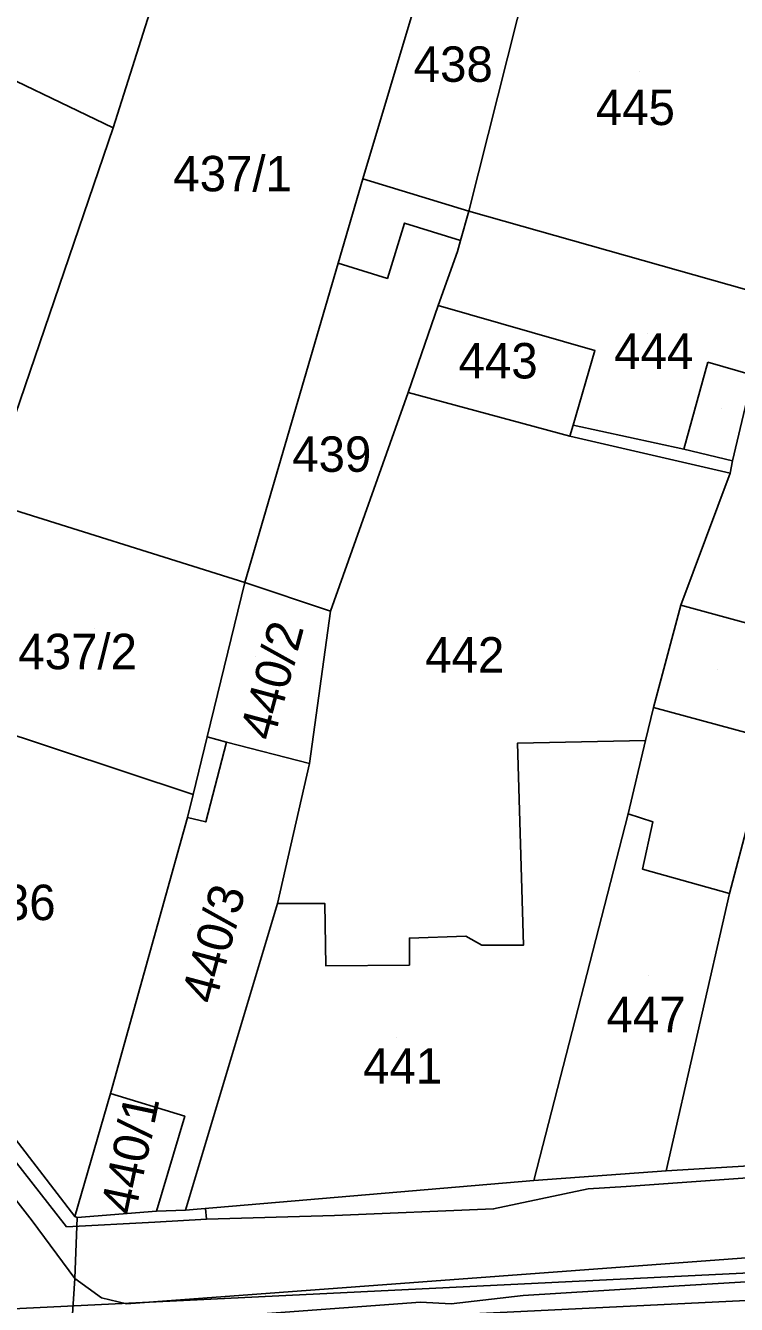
# Model space of a CAD drawing. Extents: x -263423 to -261326, y -1240067 to -1237864.
# Drawn here: x -263033.7 to -262993.6, y -1239820.5 to -1239748.3 of the extents above; entities that cross this region are included whole.
import ezdxf

# ---------------------------------------------------------------- set-up
doc = ezdxf.new("R2010")
doc.units = 0
for name, color, linetype in [('body_kn', 7, 'Continuous'), ('kladpar_druhypozemkov', 7, 'Continuous'), ('kladpar_hranice', 7, 'Continuous'), ('kladpar_parcelnecisla', 7, 'Continuous'), ('kladpar_plochy', 7, 'Continuous'), ('tarchy_linie', 7, 'Continuous'), ('zappar_hrandruhpozemk', 7, 'Continuous')]:
    doc.layers.add(name, color=color, linetype=linetype)

msp = doc.modelspace()

# ---------------------------------------------------------------- linework, layer by layer
at = {"layer": 'body_kn'}
for p, q in [((-263028.75, -1239754.07), (-263028.75, -1239754.07)), ((-263014.66, -1239756.94), (-263014.66, -1239756.94)), ((-263014.66, -1239756.94), (-263014.66, -1239756.94)), ((-263008.67, -1239758.76), (-263008.67, -1239758.76)), ((-263012.3, -1239759.44), (-263012.3, -1239759.44)), ((-263009.14, -1239760.42), (-263009.14, -1239760.42)), ((-263009.14, -1239760.42), (-263009.14, -1239760.42)), ((-263009.32, -1239761.05), (-263009.32, -1239761.05)), ((-263016.05, -1239761.7), (-263016.05, -1239761.7)), ((-263016.05, -1239761.7), (-263016.05, -1239761.7)), ((-263013.27, -1239762.56), (-263013.27, -1239762.56)), ((-263010.41, -1239764.1), (-263010.41, -1239764.1)), ((-263001.56, -1239766.63), (-263001.56, -1239766.63)), ((-263001.56, -1239766.63), (-263001.56, -1239766.63)), ((-262995.18, -1239767.3), (-262995.18, -1239767.3)), ((-263012.09, -1239769), (-263012.09, -1239769)), ((-263012.09, -1239769), (-263012.09, -1239769)), ((-263002.79, -1239770.84), (-263002.79, -1239770.84)), ((-263002.79, -1239770.84), (-263002.79, -1239770.84)), ((-263002.98, -1239771.47), (-263002.98, -1239771.47)), ((-262996.54, -1239772.2), (-262996.54, -1239772.2)), ((-262993.8, -1239772.86), (-262993.8, -1239772.86)), ((-262993.93, -1239773.56), (-262993.93, -1239773.56)), ((-263021.32, -1239779.73), (-263021.32, -1239779.73)), ((-262996.71, -1239781), (-262996.71, -1239781)), ((-263016.48, -1239781.35), (-263016.48, -1239781.35)), ((-263016.48, -1239781.35), (-263016.48, -1239781.35)), ((-262998.26, -1239786.79), (-262998.26, -1239786.79)), ((-263023.44, -1239788.44), (-263023.44, -1239788.44)), ((-263022.35, -1239788.73), (-263022.35, -1239788.73)), ((-263022.35, -1239788.73), (-263022.35, -1239788.73)), ((-263005.92, -1239788.79), (-263005.92, -1239788.79)), ((-262998.71, -1239788.64), (-262998.71, -1239788.64)), ((-263017.66, -1239789.95), (-263017.66, -1239789.95)), ((-263024.24, -1239791.7), (-263024.24, -1239791.7)), ((-263024.55, -1239792.98), (-263024.55, -1239792.98)), ((-263023.52, -1239793.24), (-263023.52, -1239793.24)), ((-262999.69, -1239792.78), (-262999.69, -1239792.78)), ((-262998.29, -1239793.23), (-262998.29, -1239793.23)), ((-262998.87, -1239795.9), (-262998.87, -1239795.9)), ((-262993.97, -1239797.27), (-262993.97, -1239797.27)), ((-262993.97, -1239797.27), (-262993.97, -1239797.27)), ((-263019.48, -1239797.84), (-263019.48, -1239797.84)), ((-263019.48, -1239797.84), (-263019.48, -1239797.84)), ((-263016.8, -1239797.85), (-263016.8, -1239797.85)), ((-263008.84, -1239799.68), (-263008.84, -1239799.68)), ((-263012.03, -1239799.79), (-263012.03, -1239799.79)), ((-263007.95, -1239800.19), (-263007.95, -1239800.19)), ((-263005.59, -1239800.2), (-263005.59, -1239800.2)), ((-263016.75, -1239801.36), (-263016.75, -1239801.36)), ((-263012.03, -1239801.32), (-263012.03, -1239801.32)), ((-263012.03, -1239801.32), (-263012.03, -1239801.32)), ((-263028.91, -1239808.56), (-263028.91, -1239808.56)), ((-263024.71, -1239809.85), (-263024.71, -1239809.85)), ((-263005, -1239813.47), (-263005, -1239813.47)), ((-262997.54, -1239812.93), (-262997.54, -1239812.93)), ((-263001.93, -1239813.95), (-263001.93, -1239813.95)), ((-262999.8, -1239813.82), (-262999.8, -1239813.82)), ((-263030.91, -1239815.51), (-263030.91, -1239815.51)), ((-263030.91, -1239815.51), (-263030.91, -1239815.51)), ((-263030.78, -1239815.57), (-263030.78, -1239815.57)), ((-263026.31, -1239815.21), (-263026.31, -1239815.21)), ((-263026.31, -1239815.21), (-263026.31, -1239815.21)), ((-263024.66, -1239815.15), (-263024.66, -1239815.15)), ((-263023.53, -1239815.05), (-263023.53, -1239815.05)), ((-263016.25, -1239815.45), (-263016.25, -1239815.45)), ((-263007.28, -1239815.08), (-263007.28, -1239815.08)), ((-263033.33, -1239815.75), (-263033.33, -1239815.75)), ((-263031.38, -1239816.09), (-263031.38, -1239816.09)), ((-263026.39, -1239815.83), (-263026.39, -1239815.83)), ((-263023.48, -1239815.66), (-263023.48, -1239815.66)), ((-263023.48, -1239815.66), (-263023.48, -1239815.66)), ((-263030.92, -1239819.01), (-263030.92, -1239819.01)), ((-263030.92, -1239819.01), (-263030.92, -1239819.01)), ((-263005.6, -1239819.97), (-263005.6, -1239819.97)), ((-262996.8, -1239819.42), (-262996.8, -1239819.42)), ((-263029.4, -1239820.1), (-263029.4, -1239820.1)), ((-263027.99, -1239820.43), (-263027.99, -1239820.43)), ((-263011.41, -1239820.35), (-263011.41, -1239820.35)), ((-263009.68, -1239820.43), (-263009.68, -1239820.43))]:
    msp.add_line(p, q, dxfattribs=at)
at = {"layer": 'kladpar_druhypozemkov'}
for p, q in [((-263009.36, -1239750.05), (-263009.36, -1239750.05)), ((-262999.05, -1239750.91), (-262999.05, -1239750.91)), ((-263021.93, -1239755.66), (-263021.93, -1239755.66)), ((-262998.6, -1239765.69), (-262998.6, -1239765.69)), ((-263006.95, -1239766.61), (-263006.95, -1239766.61)), ((-262994.43, -1239769.92), (-262994.43, -1239769.92)), ((-263016.24, -1239771.69), (-263016.24, -1239771.69)), ((-263029.8, -1239782.32), (-263029.8, -1239782.32)), ((-263008.65, -1239782.41), (-263008.65, -1239782.41)), ((-263020.71, -1239783.93), (-263020.71, -1239783.93)), ((-262994.63, -1239784.62), (-262994.63, -1239784.62)), ((-263024.41, -1239799.01), (-263024.41, -1239799.01)), ((-262998.55, -1239801.91), (-262998.55, -1239801.91)), ((-263012.75, -1239805.41), (-263012.75, -1239805.41)), ((-263028.63, -1239811.97), (-263028.63, -1239811.97))]:
    msp.add_line(p, q, dxfattribs=at)
at = {"layer": 'kladpar_hranice'}
for points in [[(-263029.37, -1239734.56), (-263023.32, -1239736.89), (-263028.75, -1239754.07), (-263037.21, -1239750.01), (-263029.37, -1239734.56)], [(-263023.32, -1239736.89), (-263010.2, -1239742.05), (-263014.66, -1239756.94), (-263016.05, -1239761.7), (-263021.32, -1239779.73), (-263035.95, -1239775.13), (-263028.75, -1239754.07), (-263023.32, -1239736.89)], [(-263009.14, -1239760.42), (-263012.3, -1239759.44), (-263013.27, -1239762.56), (-263016.05, -1239761.7), (-263014.66, -1239756.94), (-263010.2, -1239742.05), (-263004.85, -1239743.61), (-263008.67, -1239758.76), (-263009.14, -1239760.42)], [(-262988.22, -1239748.35), (-262990.81, -1239758.21), (-262991.98, -1239763.5), (-263008.67, -1239758.76), (-263004.85, -1239743.61), (-262988.22, -1239748.35)], [(-263037.21, -1239750.01), (-263028.75, -1239754.07), (-263035.95, -1239775.13), (-263039.85, -1239786.52), (-263040.11, -1239787.29), (-263043.47, -1239799.19), (-263054.13, -1239785.3), (-263048.6, -1239772.77), (-263041.97, -1239759.68), (-263038.95, -1239753.51), (-263037.21, -1239750.01)], [(-262991.98, -1239763.5), (-262992.64, -1239768.02), (-262993.8, -1239772.86), (-262993.93, -1239773.56), (-263002.98, -1239771.47), (-263002.79, -1239770.84), (-263001.56, -1239766.63), (-263010.41, -1239764.1), (-263009.32, -1239761.05), (-263009.14, -1239760.42), (-263008.67, -1239758.76), (-262991.98, -1239763.5)], [(-263016.05, -1239761.7), (-263013.27, -1239762.56), (-263012.3, -1239759.44), (-263009.14, -1239760.42), (-263009.32, -1239761.05), (-263010.41, -1239764.1), (-263012.09, -1239769), (-263016.48, -1239781.35), (-263021.32, -1239779.73), (-263016.05, -1239761.7)], [(-262986.64, -1239768.57), (-262986.9, -1239769.58), (-262986.92, -1239769.66), (-262989.92, -1239782.15), (-262990.08, -1239782.82), (-262996.71, -1239781), (-262993.93, -1239773.56), (-262993.8, -1239772.86), (-262992.64, -1239768.02), (-262991.98, -1239763.5), (-262991.81, -1239763.66), (-262991.95, -1239764.75), (-262991.23, -1239765.39), (-262990.63, -1239764.79), (-262986.64, -1239768.57)], [(-263001.56, -1239766.63), (-263002.79, -1239770.84), (-263002.98, -1239771.47), (-263012.09, -1239769), (-263010.41, -1239764.1), (-263001.56, -1239766.63)], [(-263012.09, -1239769), (-263002.98, -1239771.47), (-262993.93, -1239773.56), (-262996.71, -1239781), (-262998.26, -1239786.79), (-262998.71, -1239788.64), (-263005.92, -1239788.79), (-263005.59, -1239800.2), (-263007.95, -1239800.19), (-263008.84, -1239799.68), (-263012.03, -1239799.79), (-263012.03, -1239801.32), (-263016.75, -1239801.36), (-263016.8, -1239797.85), (-263019.48, -1239797.84), (-263017.66, -1239789.95), (-263016.48, -1239781.35), (-263012.09, -1239769)], [(-263035.95, -1239775.13), (-263021.32, -1239779.73), (-263023.44, -1239788.44), (-263024.24, -1239791.7), (-263039.85, -1239786.52), (-263035.95, -1239775.13)], [(-263016.48, -1239781.35), (-263017.66, -1239789.95), (-263022.35, -1239788.73), (-263023.52, -1239793.24), (-263024.55, -1239792.98), (-263024.24, -1239791.7), (-263023.44, -1239788.44), (-263021.32, -1239779.73), (-263016.48, -1239781.35)], [(-262990.08, -1239782.82), (-262990.53, -1239784.28), (-262991.7, -1239788.55), (-262992.86, -1239793.06), (-262993.97, -1239797.27), (-262997.54, -1239812.93), (-263005, -1239813.47), (-262999.69, -1239792.78), (-262998.71, -1239788.64), (-262998.26, -1239786.79), (-262996.71, -1239781), (-262990.08, -1239782.82)], [(-262979.38, -1239787.08), (-262981.4, -1239795.93), (-262981.91, -1239798.03), (-262983.54, -1239804.77), (-262989.46, -1239803.34), (-262991.6, -1239812.58), (-262997.54, -1239812.93), (-262993.97, -1239797.27), (-262992.86, -1239793.06), (-262991.7, -1239788.55), (-262990.53, -1239784.28), (-262979.38, -1239787.08)], [(-263043.47, -1239799.19), (-263040.11, -1239787.29), (-263039.85, -1239786.52), (-263024.24, -1239791.7), (-263024.55, -1239792.98), (-263028.91, -1239808.56), (-263030.91, -1239815.51), (-263043.47, -1239799.19)], [(-263019.48, -1239797.84), (-263024.66, -1239815.15), (-263026.31, -1239815.21), (-263024.71, -1239809.85), (-263028.91, -1239808.56), (-263024.55, -1239792.98), (-263023.52, -1239793.24), (-263022.35, -1239788.73), (-263017.66, -1239789.95), (-263019.48, -1239797.84)], [(-263012.03, -1239801.32), (-263012.03, -1239799.79), (-263008.84, -1239799.68), (-263007.95, -1239800.19), (-263005.59, -1239800.2), (-263005.92, -1239788.79), (-262998.71, -1239788.64), (-262999.69, -1239792.78), (-263005, -1239813.47), (-263024.66, -1239815.15), (-263019.48, -1239797.84), (-263016.8, -1239797.85), (-263016.75, -1239801.36), (-263012.03, -1239801.32)], [(-263043.47, -1239799.19), (-263030.91, -1239815.51)], [(-263026.31, -1239815.21), (-263030.78, -1239815.57), (-263030.91, -1239815.51), (-263028.91, -1239808.56), (-263024.71, -1239809.85), (-263026.31, -1239815.21)], [(-263031.67, -1239830.48), (-263030.92, -1239819.01), (-263030.78, -1239815.57), (-263026.31, -1239815.21), (-263024.66, -1239815.15), (-263005, -1239813.47), (-262997.54, -1239812.93), (-262991.6, -1239812.58), (-262985.42, -1239812.16), (-262979.16, -1239811.74), (-262972.66, -1239811.27), (-262966.66, -1239810.78), (-262963.47, -1239810.61), (-262960.6, -1239810.5), (-262954.1, -1239810.21), (-262947.85, -1239809.79)], [(-263030.91, -1239815.51), (-263030.78, -1239815.57), (-263030.92, -1239819.01), (-263031.67, -1239830.48)]]:
    msp.add_lwpolyline(points, dxfattribs=at)
at = {"layer": 'kladpar_plochy'}
for points in [[(-263029.37, -1239734.56), (-263023.32, -1239736.89), (-263028.75, -1239754.07), (-263037.21, -1239750.01)], [(-263023.32, -1239736.89), (-263010.2, -1239742.05), (-263014.66, -1239756.94), (-263016.05, -1239761.7), (-263021.32, -1239779.73), (-263035.95, -1239775.13), (-263028.75, -1239754.07)], [(-263009.14, -1239760.42), (-263012.3, -1239759.44), (-263013.27, -1239762.56), (-263016.05, -1239761.7), (-263014.66, -1239756.94), (-263010.2, -1239742.05), (-263004.85, -1239743.61), (-263008.67, -1239758.76)], [(-262988.22, -1239748.35), (-262990.81, -1239758.21), (-262991.98, -1239763.5), (-263008.67, -1239758.76), (-263004.85, -1239743.61)], [(-263037.21, -1239750.01), (-263028.75, -1239754.07), (-263035.95, -1239775.13), (-263039.85, -1239786.52), (-263040.11, -1239787.29), (-263043.47, -1239799.19), (-263054.13, -1239785.3), (-263048.6, -1239772.77), (-263041.97, -1239759.68), (-263038.95, -1239753.51)], [(-262991.98, -1239763.5), (-262992.64, -1239768.02), (-262993.8, -1239772.86), (-262993.93, -1239773.56), (-263002.98, -1239771.47), (-263002.79, -1239770.84), (-263001.56, -1239766.63), (-263010.41, -1239764.1), (-263009.32, -1239761.05), (-263009.14, -1239760.42), (-263008.67, -1239758.76)], [(-263016.05, -1239761.7), (-263013.27, -1239762.56), (-263012.3, -1239759.44), (-263009.14, -1239760.42), (-263009.32, -1239761.05), (-263010.41, -1239764.1), (-263012.09, -1239769), (-263016.48, -1239781.35), (-263021.32, -1239779.73)], [(-262986.64, -1239768.57), (-262986.9, -1239769.58), (-262986.92, -1239769.66), (-262989.92, -1239782.15), (-262990.08, -1239782.82), (-262996.71, -1239781), (-262993.93, -1239773.56), (-262993.8, -1239772.86), (-262992.64, -1239768.02), (-262991.98, -1239763.5), (-262991.81, -1239763.66), (-262991.95, -1239764.75), (-262991.23, -1239765.39), (-262990.63, -1239764.79)], [(-263001.56, -1239766.63), (-263002.79, -1239770.84), (-263002.98, -1239771.47), (-263012.09, -1239769), (-263010.41, -1239764.1)], [(-263012.09, -1239769), (-263002.98, -1239771.47), (-262993.93, -1239773.56), (-262996.71, -1239781), (-262998.26, -1239786.79), (-262998.71, -1239788.64), (-263005.92, -1239788.79), (-263005.59, -1239800.2), (-263007.95, -1239800.19), (-263008.84, -1239799.68), (-263012.03, -1239799.79), (-263012.03, -1239801.32), (-263016.75, -1239801.36), (-263016.8, -1239797.85), (-263019.48, -1239797.84), (-263017.66, -1239789.95), (-263016.48, -1239781.35)], [(-263035.95, -1239775.13), (-263021.32, -1239779.73), (-263023.44, -1239788.44), (-263024.24, -1239791.7), (-263039.85, -1239786.52)], [(-263016.48, -1239781.35), (-263017.66, -1239789.95), (-263022.35, -1239788.73), (-263023.52, -1239793.24), (-263024.55, -1239792.98), (-263024.24, -1239791.7), (-263023.44, -1239788.44), (-263021.32, -1239779.73)], [(-262990.08, -1239782.82), (-262990.53, -1239784.28), (-262991.7, -1239788.55), (-262992.86, -1239793.06), (-262993.97, -1239797.27), (-262997.54, -1239812.93), (-263005, -1239813.47), (-262999.69, -1239792.78), (-262998.71, -1239788.64), (-262998.26, -1239786.79), (-262996.71, -1239781)], [(-262979.38, -1239787.08), (-262981.4, -1239795.93), (-262981.91, -1239798.03), (-262983.54, -1239804.77), (-262989.46, -1239803.34), (-262991.6, -1239812.58), (-262997.54, -1239812.93), (-262993.97, -1239797.27), (-262992.86, -1239793.06), (-262991.7, -1239788.55), (-262990.53, -1239784.28)], [(-263043.47, -1239799.19), (-263040.11, -1239787.29), (-263039.85, -1239786.52), (-263024.24, -1239791.7), (-263024.55, -1239792.98), (-263028.91, -1239808.56), (-263030.91, -1239815.51)], [(-263019.48, -1239797.84), (-263024.66, -1239815.15), (-263026.31, -1239815.21), (-263024.71, -1239809.85), (-263028.91, -1239808.56), (-263024.55, -1239792.98), (-263023.52, -1239793.24), (-263022.35, -1239788.73), (-263017.66, -1239789.95)], [(-263012.03, -1239801.32), (-263012.03, -1239799.79), (-263008.84, -1239799.68), (-263007.95, -1239800.19), (-263005.59, -1239800.2), (-263005.92, -1239788.79), (-262998.71, -1239788.64), (-262999.69, -1239792.78), (-263005, -1239813.47), (-263024.66, -1239815.15), (-263019.48, -1239797.84), (-263016.8, -1239797.85), (-263016.75, -1239801.36)], [(-263026.31, -1239815.21), (-263030.78, -1239815.57), (-263030.91, -1239815.51), (-263028.91, -1239808.56), (-263024.71, -1239809.85)]]:
    msp.add_lwpolyline(points, close=True, dxfattribs=at)
for points in [[(-263043.47, -1239799.19), (-263030.91, -1239815.51), (-263030.78, -1239815.57), (-263030.92, -1239819.01), (-263031.67, -1239830.48)], [(-263031.67, -1239830.48), (-263030.92, -1239819.01), (-263030.78, -1239815.57), (-263026.31, -1239815.21), (-263024.66, -1239815.15), (-263005, -1239813.47), (-262997.54, -1239812.93), (-262991.6, -1239812.58), (-262985.42, -1239812.16), (-262979.16, -1239811.74), (-262972.66, -1239811.27), (-262966.66, -1239810.78), (-262963.47, -1239810.61), (-262960.6, -1239810.5), (-262954.1, -1239810.21), (-262947.85, -1239809.79), (-262945.55, -1239809.61), (-262941.85, -1239809.44), (-262937.9, -1239809.08), (-262935.03, -1239808.9), (-262929.16, -1239808.4), (-262927.24, -1239808.23)]]:
    msp.add_lwpolyline(points, dxfattribs=at)
at = {"layer": 'tarchy_linie'}
msp.add_line((-263023.48, -1239815.66), (-263023.53, -1239815.05), dxfattribs=at)
for points in [[(-263038.73, -1239806.72), (-263031.38, -1239816.09), (-263026.39, -1239815.83), (-263023.48, -1239815.66), (-263016.25, -1239815.45), (-263007.28, -1239815.08), (-263001.93, -1239813.95), (-262999.8, -1239813.82), (-262990.57, -1239813.15), (-262978.09, -1239812.41), (-262977.23, -1239813.17), (-262966.58, -1239812.41), (-262965.44, -1239811.68), (-262964.69, -1239811.62), (-262963.25, -1239812.34), (-262962.69, -1239812.33), (-262954.08, -1239811.71), (-262947.55, -1239811.24), (-262941.7, -1239810.91), (-262936.84, -1239810.59), (-262926.96, -1239809.83)], [(-263040.71, -1239822.61), (-263028.21, -1239821.58), (-263011.41, -1239820.35), (-263009.68, -1239820.43), (-263005.6, -1239819.97), (-262996.8, -1239819.42), (-262990.52, -1239819.05), (-262982.27, -1239818.21), (-262974.9, -1239817.94), (-262961.71, -1239816.9), (-262957.13, -1239816.67), (-262951.22, -1239816.14), (-262935.08, -1239814.96), (-262920.83, -1239813.88), (-262915.8, -1239814.33), (-262912.45, -1239815.09), (-262910.37, -1239815.48), (-262904.67, -1239816.87), (-262900.33, -1239817.77), (-262879.71, -1239823.02)], [(-263037.12, -1239820.85), (-262910.42, -1239814.67), (-262904.24, -1239815.14), (-262880.51, -1239820.63), (-262880.88, -1239822.14), (-262880.99, -1239822.6), (-262877.97, -1239823.34), (-262877.85, -1239822.84), (-262877.48, -1239821.33), (-262844.24, -1239829.02), (-262814.48, -1239915.4), (-262784.13, -1239904.88), (-262744.13, -1239891.33), (-262716.19, -1239882.12)], [(-263042.81, -1239822.68), (-262910.44, -1239816.22), (-262904.59, -1239816.65)]]:
    msp.add_lwpolyline(points, dxfattribs=at)
at = {"layer": 'zappar_hrandruhpozemk'}
for p, q in [((-263014.66, -1239756.94), (-263008.67, -1239758.76)), ((-262996.54, -1239772.2), (-262995.18, -1239767.3)), ((-262995.18, -1239767.3), (-262992.64, -1239768.02)), ((-263002.79, -1239770.84), (-262996.54, -1239772.2)), ((-262996.54, -1239772.2), (-262993.8, -1239772.86)), ((-262991.7, -1239788.55), (-262998.26, -1239786.79)), ((-263022.35, -1239788.73), (-263023.44, -1239788.44)), ((-262993.97, -1239797.27), (-262998.87, -1239795.9))]:
    msp.add_line(p, q, dxfattribs=at)
for points in [[(-263030.92, -1239819.01), (-263033.33, -1239815.75), (-263056.05, -1239786.57)], [(-262998.87, -1239795.9), (-262998.29, -1239793.23), (-262999.69, -1239792.78)], [(-262973, -1239816.36), (-263027.99, -1239820.43), (-263029.4, -1239820.1), (-263030.92, -1239819.01)]]:
    msp.add_lwpolyline(points, dxfattribs=at)

# ---------------------------------------------------------------- texts
at = {"layer": 'kladpar_parcelnecisla'}
for s, p in [('438', (-263011.785, -1239751.47)), ('445', (-263001.504, -1239753.91)), ('437/1', (-263025.355, -1239757.65)), ('444', (-263000.469, -1239767.67)), ('443', (-263009.251, -1239768.21)), ('439', (-263018.641, -1239773.48)), ('437/2', (-263034.101, -1239784.62)), ('442', (-263011.136, -1239784.81)), ('436', (-263036.461, -1239798.78)), ('447', (-263000.902, -1239805.11)), ('441', (-263014.64, -1239808.01))]:
    msp.add_text(s, height=2, dxfattribs=at).set_placement(p)
for s, rotation, p in [('440/2', 75, (-263019.7, -1239788.734)), ('440/3', 75, (-263022.994, -1239803.589)), ('440/1', 78, (-263027.523, -1239815.489))]:
    msp.add_text(s, height=2, rotation=rotation, dxfattribs=at).set_placement(p)

doc.saveas('drawing.dxf')
